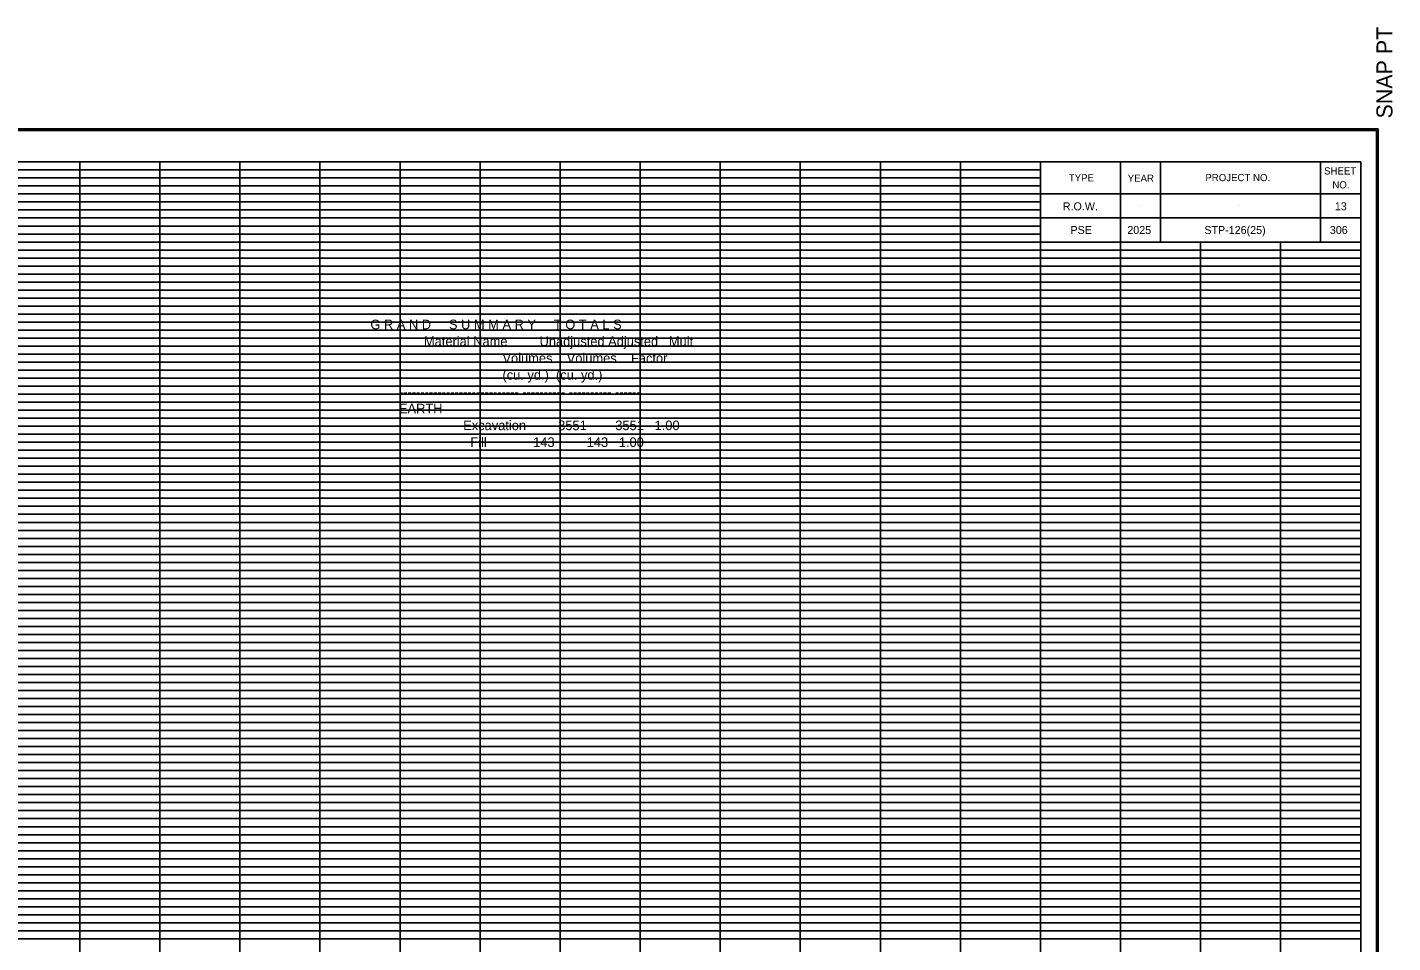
# Model space of a CAD drawing. Extents: x 980 to 2064, y 978 to 2267.
# Drawn here: x 1893.4 to 2064, y 1632.5 to 1746.8 of the extents above; entities that cross this region are included whole.
import ezdxf

# ---------------------------------------------------------------- set-up
doc = ezdxf.new("R2010")
doc.units = 0
for name, color, linetype in [('Default', 7, 'Continuous'), ('DESIGN - SCRATCH - User 1', 7, 'Continuous'), ('DESIGN - SHEET - Corner Text', 7, 'Continuous'), ('DESIGN - SHEET - Light Grid', 7, 'Continuous'), ('DESIGN - SHEET - Linework', 7, 'Continuous'), ('DESIGN - SHEET - Plot Shape', 7, 'Continuous'), ('DESIGN - TYPICAL - Text', 7, 'Continuous')]:
    doc.layers.add(name, color=color, linetype=linetype)

# ---------------------------------------------------------------- blocks, each defined once
blk = doc.blocks.new('XSTSHT')
at = {"layer": 'DESIGN - SCRATCH - User 1'}
for p, q in [((28.5, 20.45), (28.5, 20.45)), ((29.24, 20.45), (29.24, 20.45)), ((30.49, 20.45), (30.49, 20.45)), ((31.74, 20.45), (31.74, 20.45)), ((28.5, 20.15), (28.5, 20.15)), ((29.24, 20.15), (29.24, 20.15)), ((30.49, 20.15), (30.49, 20.15)), ((31.74, 20.15), (31.74, 20.15))]:
    blk.add_line(p, q, dxfattribs=at)
at = {"layer": 'DESIGN - SHEET - Light Grid'}
for p, q in [((8, 20.9), (16, 20.9)), ((16, 20.9), (24, 20.9)), ((24, 20.9), (28, 20.9)), ((8, 20.8), (16, 20.8)), ((8, 20.7), (16, 20.7)), ((16, 20.8), (24, 20.8)), ((16, 20.7), (24, 20.7)), ((24, 20.8), (28, 20.8)), ((24, 20.7), (28, 20.7)), ((8, 20.6), (16, 20.6)), ((8, 20.5), (16, 20.5)), ((16, 20.6), (24, 20.6)), ((16, 20.5), (24, 20.5)), ((24, 20.6), (28, 20.6)), ((24, 20.5), (28, 20.5)), ((8, 20.4), (16, 20.4)), ((8, 20.3), (16, 20.3)), ((16, 20.4), (24, 20.4)), ((16, 20.3), (24, 20.3)), ((24, 20.4), (28, 20.4)), ((24, 20.3), (28, 20.3)), ((8, 20.2), (16, 20.2)), ((16, 20.2), (24, 20.2)), ((24, 20.2), (28, 20.2)), ((8, 20.1), (16, 20.1)), ((16, 20.1), (24, 20.1)), ((24, 20.1), (28, 20.1)), ((8, 19.9), (16, 19.9)), ((8, 19.8), (16, 19.8)), ((16, 19.9), (24, 19.9)), ((16, 19.8), (24, 19.8)), ((24, 19.9), (32, 19.9)), ((24, 19.8), (32, 19.8)), ((8, 19.7), (16, 19.7)), ((16, 19.7), (24, 19.7)), ((24, 19.7), (32, 19.7)), ((8, 19.6), (16, 19.6)), ((8, 19.5), (16, 19.5)), ((16, 19.6), (24, 19.6)), ((16, 19.5), (24, 19.5)), ((24, 19.6), (32, 19.6)), ((24, 19.5), (32, 19.5)), ((8, 19.4), (16, 19.4)), ((8, 19.3), (16, 19.3)), ((16, 19.4), (24, 19.4)), ((16, 19.3), (24, 19.3)), ((24, 19.4), (32, 19.4)), ((24, 19.3), (32, 19.3)), ((8, 19.2), (16, 19.2)), ((16, 19.2), (24, 19.2)), ((24, 19.2), (32, 19.2)), ((8, 19.1), (16, 19.1)), ((16, 19.1), (24, 19.1)), ((24, 19.1), (32, 19.1)), ((8, 18.9), (16, 18.9)), ((8, 18.8), (16, 18.8)), ((16, 18.9), (24, 18.9)), ((16, 18.8), (24, 18.8)), ((24, 18.9), (32, 18.9)), ((24, 18.8), (32, 18.8)), ((8, 18.7), (16, 18.7)), ((8, 18.6), (16, 18.6)), ((16, 18.7), (24, 18.7)), ((16, 18.6), (24, 18.6)), ((24, 18.7), (32, 18.7)), ((24, 18.6), (32, 18.6)), ((8, 18.5), (16, 18.5)), ((16, 18.5), (24, 18.5)), ((24, 18.5), (32, 18.5)), ((8, 18.4), (16, 18.4)), ((8, 18.3), (16, 18.3)), ((16, 18.4), (24, 18.4)), ((16, 18.3), (24, 18.3)), ((24, 18.4), (32, 18.4)), ((24, 18.3), (32, 18.3)), ((8, 18.2), (16, 18.2)), ((8, 18.1), (16, 18.1)), ((16, 18.2), (24, 18.2)), ((16, 18.1), (24, 18.1)), ((24, 18.2), (32, 18.2)), ((24, 18.1), (32, 18.1)), ((8, 17.9), (16, 17.9)), ((8, 17.8), (16, 17.8)), ((16, 17.9), (24, 17.9)), ((16, 17.8), (24, 17.8)), ((24, 17.9), (32, 17.9)), ((24, 17.8), (32, 17.8)), ((8, 17.7), (16, 17.7)), ((8, 17.6), (16, 17.6)), ((16, 17.7), (24, 17.7)), ((16, 17.6), (24, 17.6)), ((24, 17.7), (32, 17.7)), ((24, 17.6), (32, 17.6)), ((8, 17.5), (16, 17.5)), ((8, 17.4), (16, 17.4)), ((16, 17.5), (24, 17.5)), ((16, 17.4), (24, 17.4)), ((24, 17.5), (32, 17.5)), ((24, 17.4), (32, 17.4)), ((8, 17.3), (16, 17.3)), ((16, 17.3), (24, 17.3)), ((24, 17.3), (32, 17.3)), ((8, 17.2), (16, 17.2)), ((8, 17.1), (16, 17.1)), ((16, 17.2), (24, 17.2)), ((16, 17.1), (24, 17.1)), ((24, 17.2), (32, 17.2)), ((24, 17.1), (32, 17.1)), ((8, 16.9), (16, 16.9)), ((16, 16.9), (24, 16.9)), ((24, 16.9), (32, 16.9)), ((8, 16.8), (16, 16.8)), ((16, 16.8), (24, 16.8)), ((24, 16.8), (32, 16.8)), ((8, 16.7), (16, 16.7)), ((8, 16.6), (16, 16.6)), ((16, 16.7), (24, 16.7)), ((16, 16.6), (24, 16.6)), ((24, 16.7), (32, 16.7)), ((24, 16.6), (32, 16.6)), ((8, 16.5), (16, 16.5)), ((8, 16.4), (16, 16.4)), ((16, 16.5), (24, 16.5)), ((16, 16.4), (24, 16.4)), ((24, 16.5), (32, 16.5)), ((24, 16.4), (32, 16.4)), ((8, 16.3), (16, 16.3)), ((16, 16.3), (24, 16.3)), ((24, 16.3), (32, 16.3)), ((8, 16.2), (16, 16.2)), ((8, 16.1), (16, 16.1)), ((16, 16.2), (24, 16.2)), ((16, 16.1), (24, 16.1)), ((24, 16.2), (32, 16.2)), ((24, 16.1), (32, 16.1)), ((8, 15.9), (16, 15.9)), ((16, 15.9), (24, 15.9)), ((24, 15.9), (32, 15.9)), ((8, 15.8), (16, 15.8)), ((8, 15.7), (16, 15.7)), ((16, 15.8), (24, 15.8)), ((16, 15.7), (24, 15.7)), ((24, 15.8), (32, 15.8)), ((24, 15.7), (32, 15.7)), ((8, 15.6), (16, 15.6)), ((16, 15.6), (24, 15.6)), ((24, 15.6), (32, 15.6)), ((8, 15.5), (16, 15.5)), ((8, 15.4), (16, 15.4)), ((16, 15.5), (24, 15.5)), ((16, 15.4), (24, 15.4)), ((24, 15.5), (32, 15.5)), ((24, 15.4), (32, 15.4)), ((8, 15.3), (16, 15.3)), ((8, 15.2), (16, 15.2)), ((16, 15.3), (24, 15.3)), ((16, 15.2), (24, 15.2)), ((24, 15.3), (32, 15.3)), ((24, 15.2), (32, 15.2)), ((8, 15.1), (16, 15.1)), ((16, 15.1), (24, 15.1)), ((24, 15.1), (32, 15.1)), ((8, 14.9), (16, 14.9)), ((16, 14.9), (24, 14.9)), ((24, 14.9), (32, 14.9)), ((8, 14.8), (16, 14.8)), ((8, 14.7), (16, 14.7)), ((16, 14.8), (24, 14.8)), ((16, 14.7), (24, 14.7)), ((24, 14.8), (32, 14.8)), ((24, 14.7), (32, 14.7)), ((8, 14.6), (16, 14.6)), ((8, 14.5), (16, 14.5)), ((16, 14.6), (24, 14.6)), ((16, 14.5), (24, 14.5)), ((24, 14.6), (32, 14.6)), ((24, 14.5), (32, 14.5)), ((8, 14.4), (16, 14.4)), ((16, 14.4), (24, 14.4)), ((24, 14.4), (32, 14.4)), ((8, 14.3), (16, 14.3)), ((8, 14.2), (16, 14.2)), ((16, 14.3), (24, 14.3)), ((16, 14.2), (24, 14.2)), ((24, 14.3), (32, 14.3)), ((24, 14.2), (32, 14.2)), ((8, 14.1), (16, 14.1)), ((16, 14.1), (24, 14.1)), ((24, 14.1), (32, 14.1)), ((8, 13.9), (16, 13.9)), ((16, 13.9), (24, 13.9)), ((24, 13.9), (32, 13.9)), ((8, 13.8), (16, 13.8)), ((8, 13.7), (16, 13.7)), ((16, 13.8), (24, 13.8)), ((16, 13.7), (24, 13.7)), ((24, 13.8), (32, 13.8)), ((24, 13.7), (32, 13.7)), ((8, 13.6), (16, 13.6)), ((8, 13.5), (16, 13.5)), ((16, 13.6), (24, 13.6)), ((16, 13.5), (24, 13.5)), ((24, 13.6), (32, 13.6)), ((24, 13.5), (32, 13.5)), ((8, 13.4), (16, 13.4)), ((16, 13.4), (24, 13.4)), ((24, 13.4), (32, 13.4)), ((8, 13.3), (16, 13.3)), ((8, 13.2), (16, 13.2)), ((16, 13.3), (24, 13.3)), ((16, 13.2), (24, 13.2)), ((24, 13.3), (32, 13.3)), ((24, 13.2), (32, 13.2)), ((8, 13.1), (16, 13.1)), ((16, 13.1), (24, 13.1)), ((24, 13.1), (32, 13.1)), ((8, 12.9), (16, 12.9)), ((8, 12.8), (16, 12.8)), ((16, 12.9), (24, 12.9)), ((16, 12.8), (24, 12.8)), ((24, 12.9), (32, 12.9)), ((24, 12.8), (32, 12.8)), ((8, 12.7), (16, 12.7)), ((16, 12.7), (24, 12.7)), ((24, 12.7), (32, 12.7)), ((8, 12.6), (16, 12.6)), ((8, 12.5), (16, 12.5)), ((16, 12.6), (24, 12.6)), ((16, 12.5), (24, 12.5)), ((24, 12.6), (32, 12.6)), ((24, 12.5), (32, 12.5)), ((8, 12.4), (16, 12.4)), ((8, 12.3), (16, 12.3)), ((16, 12.4), (24, 12.4)), ((16, 12.3), (24, 12.3)), ((24, 12.4), (32, 12.4)), ((24, 12.3), (32, 12.3)), ((8, 12.2), (16, 12.2)), ((16, 12.2), (24, 12.2)), ((24, 12.2), (32, 12.2)), ((8, 12.1), (16, 12.1)), ((16, 12.1), (24, 12.1)), ((24, 12.1), (32, 12.1)), ((8, 11.9), (16, 11.9)), ((8, 11.8), (16, 11.8)), ((16, 11.9), (24, 11.9)), ((16, 11.8), (24, 11.8)), ((24, 11.9), (32, 11.9)), ((24, 11.8), (32, 11.8)), ((8, 11.7), (16, 11.7)), ((8, 11.6), (16, 11.6)), ((16, 11.7), (24, 11.7)), ((16, 11.6), (24, 11.6)), ((24, 11.7), (32, 11.7)), ((24, 11.6), (32, 11.6)), ((8, 11.5), (16, 11.5)), ((16, 11.5), (24, 11.5)), ((24, 11.5), (32, 11.5)), ((8, 11.4), (16, 11.4)), ((8, 11.3), (16, 11.3)), ((16, 11.4), (24, 11.4)), ((16, 11.3), (24, 11.3)), ((24, 11.4), (32, 11.4)), ((24, 11.3), (32, 11.3))]:
    blk.add_line(p, q, dxfattribs=at)
at = {"layer": 'DESIGN - SHEET - Linework'}
for p, q in [((-1.823, 21.414), (32.217, 21.414)), ((32.217, 21.414), (32.217, -0.414)), ((16, 0), (16, 21)), ((17, 0), (17, 21)), ((18, 0), (18, 21)), ((19, 0), (19, 21)), ((20, 0), (20, 21)), ((21, 0), (21, 21)), ((22, 0), (22, 21)), ((23, 0), (23, 21)), ((24, 0), (24, 21)), ((25, 0), (25, 21)), ((26, 0), (26, 21)), ((27, 0), (27, 21)), ((0, 20), (28, 20)), ((28, 0), (28, 20)), ((29, 0), (29, 20)), ((30, 0), (30, 20)), ((31, 0), (31, 20)), ((0, 19), (32, 19)), ((0, 18), (32, 18)), ((0, 17), (32, 17)), ((0, 16), (32, 16)), ((0, 15), (32, 15)), ((0, 14), (32, 14)), ((0, 13), (32, 13)), ((0, 12), (32, 12))]:
    blk.add_line(p, q, dxfattribs=at)
for points in [[(0, 21), (0, 0), (32, 0), (32, 21), (0, 21)], [(28, 21), (28, 20), (32, 20), (32, 21), (31.5, 21), (31.5, 20), (29.5, 20), (29.5, 21), (29, 21), (29, 20), (32, 20), (28, 20), (28, 20.3), (32, 20.3), (32, 20.6), (28, 20.6)]]:
    blk.add_lwpolyline(points, dxfattribs=at)
at = {"layer": 'DESIGN - SHEET - Plot Shape'}
for points in [[(-1.803, 21.394), (32.197, 21.394), (32.197, -0.394), (-1.803, -0.394)], [(-0.85, 21), (32, 21), (32, -0.25), (-0.85, -0.25)]]:
    blk.add_lwpolyline(points, close=True, dxfattribs=at)
at = {"layer": 'DESIGN - SHEET - Corner Text'}
blk.add_text('  SNAP PT', height=0.2, rotation=90, dxfattribs=at).set_placement((32.397, 21.394))
for s, p in [('TYPE', (28.354, 20.756)), ('YEAR', (29.09, 20.752)), ('PROJECT NO.', (30.06, 20.76)), ('SHEET', (31.543, 20.843)), ('NO.', (31.646, 20.669))]:
    blk.add_text(s, height=0.09, dxfattribs=at).set_placement(p)

msp = doc.modelspace()

# ---------------------------------------------------------------- block references
at = {"layer": 'Default', "xscale": 10, "yscale": 10}
msp.add_blockref('XSTSHT', (1740, 1520), dxfattribs=at)

# ---------------------------------------------------------------- texts
at = {"layer": 'DESIGN - SHEET - Corner Text'}
for s, p in [('R.O.W.', (2022.79, 1723.96)), ('13', (2056.77, 1723.96)), ('PSE', (2023.75, 1721)), ('2025', (2030.85, 1721)), ('STP-126(25)', (2040.47, 1721)), ('306', (2056.15, 1721))]:
    msp.add_text(s, height=1, dxfattribs=at).set_placement(p)
at = {"layer": 'DESIGN - TYPICAL - Text'}
for s, p in [('G R A N D     S U M M A R Y     T O T A L S', (1936.3, 1709.11)), ('               Material Name         Unadjusted Adjusted   Mult', (1936.3, 1707.01)), ('                                     Volumes    Volumes    Factor', (1936.3, 1704.91)), ('                                     (cu. yd.)  (cu. yd.)', (1936.3, 1702.81)), ('        ---------------------------- ---------- ---------- ------', (1936.3, 1700.71)), ('        EARTH', (1936.3, 1698.61)), ('                          Excavation         3551        3551   1.00', (1936.3, 1696.51)), ('                            Fill             143         143   1.00', (1936.3, 1694.41))]:
    msp.add_text(s, height=1.2, dxfattribs=at).set_placement(p)

doc.saveas('drawing.dxf')
